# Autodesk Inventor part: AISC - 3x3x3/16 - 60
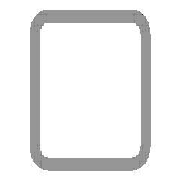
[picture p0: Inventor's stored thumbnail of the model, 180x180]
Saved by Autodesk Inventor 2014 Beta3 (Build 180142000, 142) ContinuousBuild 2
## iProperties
Created: 2011-01
Part Number: AISC - 3x3x3/16 - 60
Material: Steel, Mild
Description: Tube
Document SubType Name: Modeling
Standard: ANSI
Designer: Beta-8540w
Standards Organization: ANSI
Language: en-US
Size Designation: 3x3x3/16
Categories: <MemberInstance><Categories><Category DisplayName="Structural Shapes" InternalName="089c4875-fa83-4c05-b084-43b9cc11f5ed" Mnemonic="GRDR"><CategoryParameter Dis
Stock Number: 3x3x3/16
Density: 7.86 g/cm^3
Appearance: Steel
IsCustomPart: 1
_CCFamilyMember: 9
_CCFamilyDisplayName: ANSI AISC (Square) - Tube
_FrameMemberDoc: Frame Member File
_Version: 15.0.0
_GetPNFromCC: 1
G_L: 60.000 in
G_W: 3.000 in
G_H: 3.000 in
Author: Beta-8540w
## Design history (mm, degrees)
node "Start plane"
node "End plane"
sketch "Sketch"
  geometry: L1 (-38.1, -28.575)-(-38.1, 28.575); L2 (-28.575, 38.1)-(28.575, 38.1); L3 (38.1, 28.575)-(38.1, -28.575); L4 (28.575, -38.1)-(-28.575, -38.1); L5 (-28.575, 33.337)-(28.575, 33.338); L6 (33.338, 28.575)-(33.338, -28.575); L7 (28.575, -33.337)-(-28.575, -33.338); L8 (-33.338, -28.575)-(-33.338, 28.575); L9 (0, 56.102)-(0, -56.102) reference; L10 (-56.102, 0)-(56.102, 0) reference; A1 r 9.525 centre (-28.575, -28.575) between (-38.1, -28.575) and (-28.575, -38.1); A2 r 9.525 centre (-28.575, 28.575) between (-28.575, 38.1) and (-38.1, 28.575); A3 r 9.525 centre (28.575, 28.575) between (38.1, 28.575) and (28.575, 38.1); A4 r 9.525 centre (28.575, -28.575) between (28.575, -38.1) and (38.1, -28.575); A5 r 4.763 centre (-28.575, 28.575) between (-28.575, 33.337) and (-33.338, 28.575); A6 r 4.763 centre (28.575, 28.575) between (33.338, 28.575) and (28.575, 33.338); A7 r 4.763 centre (28.575, -28.575) between (28.575, -33.337) and (33.338, -28.575); A8 r 4.763 centre (-28.575, -28.575) between (-33.338, -28.575) and (-28.575, -33.338)
  constraints: 16 end point, 16 point on circle, 8 centre point, 8 tangent, 4 parallel, 3 equal radius, 2 perpendicular, 7 other
  dimensions: "d10" = 76.2 distance between parallel lines of L2 L4 (= G_H); "d11" = 76.2 distance between parallel lines of L1 L3 (= G_W); "d12" = 4.7625 distance between parallel lines of L3 L6 (= G_T); "d15" = 38.1 distance between parallel lines of L2 L10 (= 0.5 x d10); "d16" = 38.1 distance between parallel lines of L9 L3 (= 0.5 x d11); "d17" = 9.525 radius of A1 (= G_IR)
extrude "Body" new body sketch "Sketch" stored distance "d3" = 1524 (= G_L); taper "d4" = 0 deg
node "Driven Length"
  sketch "Sketch3"
    geometry: L1 (0, 0)-(10, 0) reference
    constraints: 2 end point, 1 horizontal
  workplane "Work Plane3"
  sketch "Sketch4"
    geometry: L1 (-2, 0)-(12, 0) reference; L2 (-2, 1524)-(12, 1524) reference
    dimensions: "d19" = 1524 distance between parallel lines of L1 L2 (derived)
body "Solid1"
other parameters: "G_W" = 76.2 [user parameter; used in 1 equation term], "G_H" = 76.2 [user parameter; used in 1 equation term], "G_T" = 4.7625 [user parameter; used in 1 equation term], "G_IR" = 9.525 [user parameter; used in 1 equation term], "G_L" = 1524 (= d19) [user parameter; used in 1 equation term], "G_OFFSET_START" = 0 [user parameter; used in 1 equation term], "G_OFFSET_END" = 0 [user parameter; used in 1 equation term], "d13" = 0 (computed from G_OFFSET_START), "d14" = 1524 (= G_OFFSET_END + B_L), "B_L" = 1524 [user parameter; used in 1 equation term], "d18" = 90 deg
